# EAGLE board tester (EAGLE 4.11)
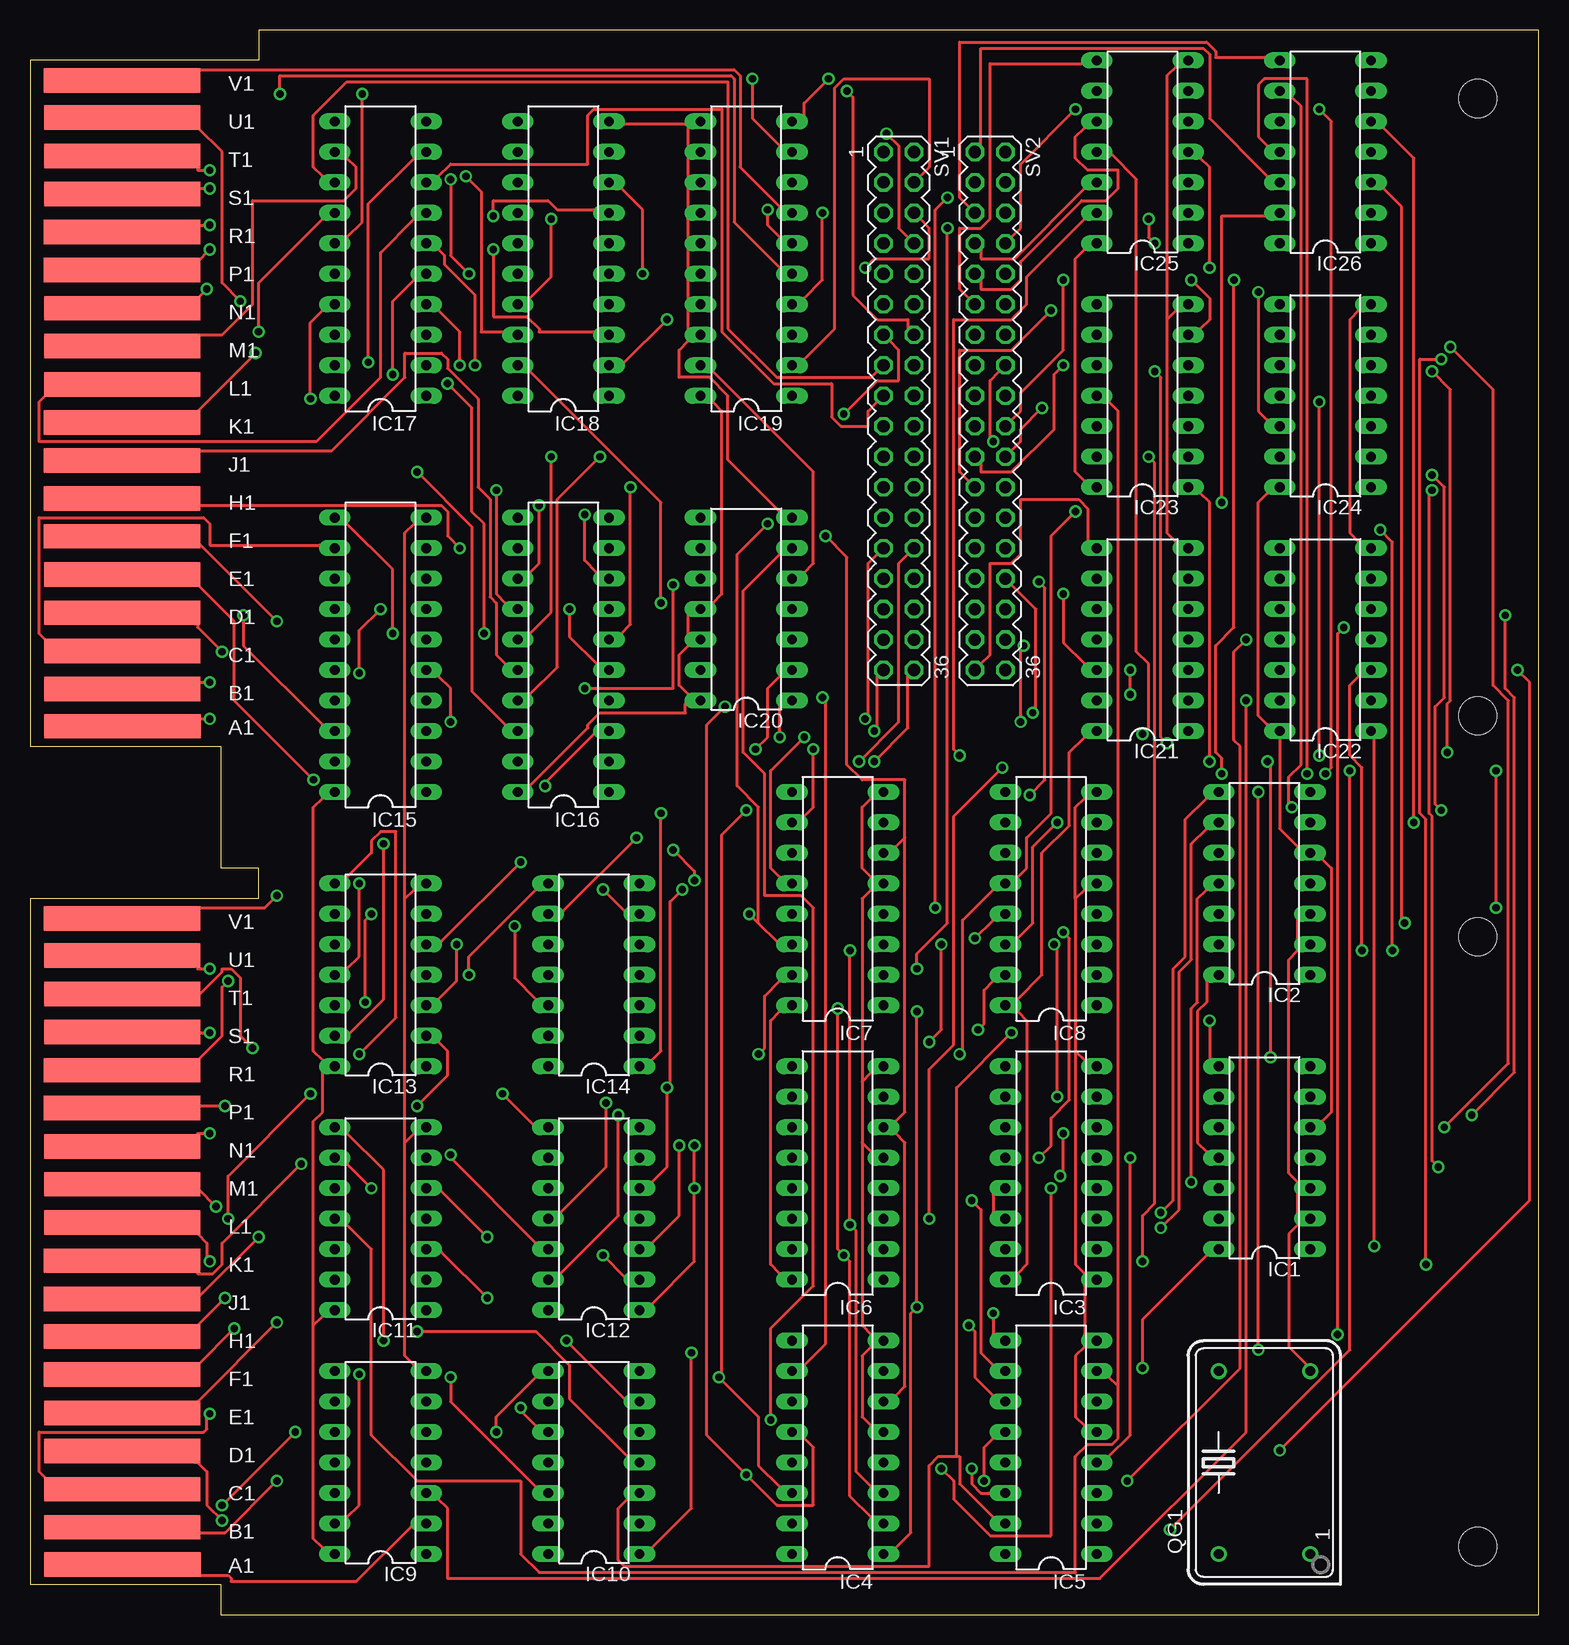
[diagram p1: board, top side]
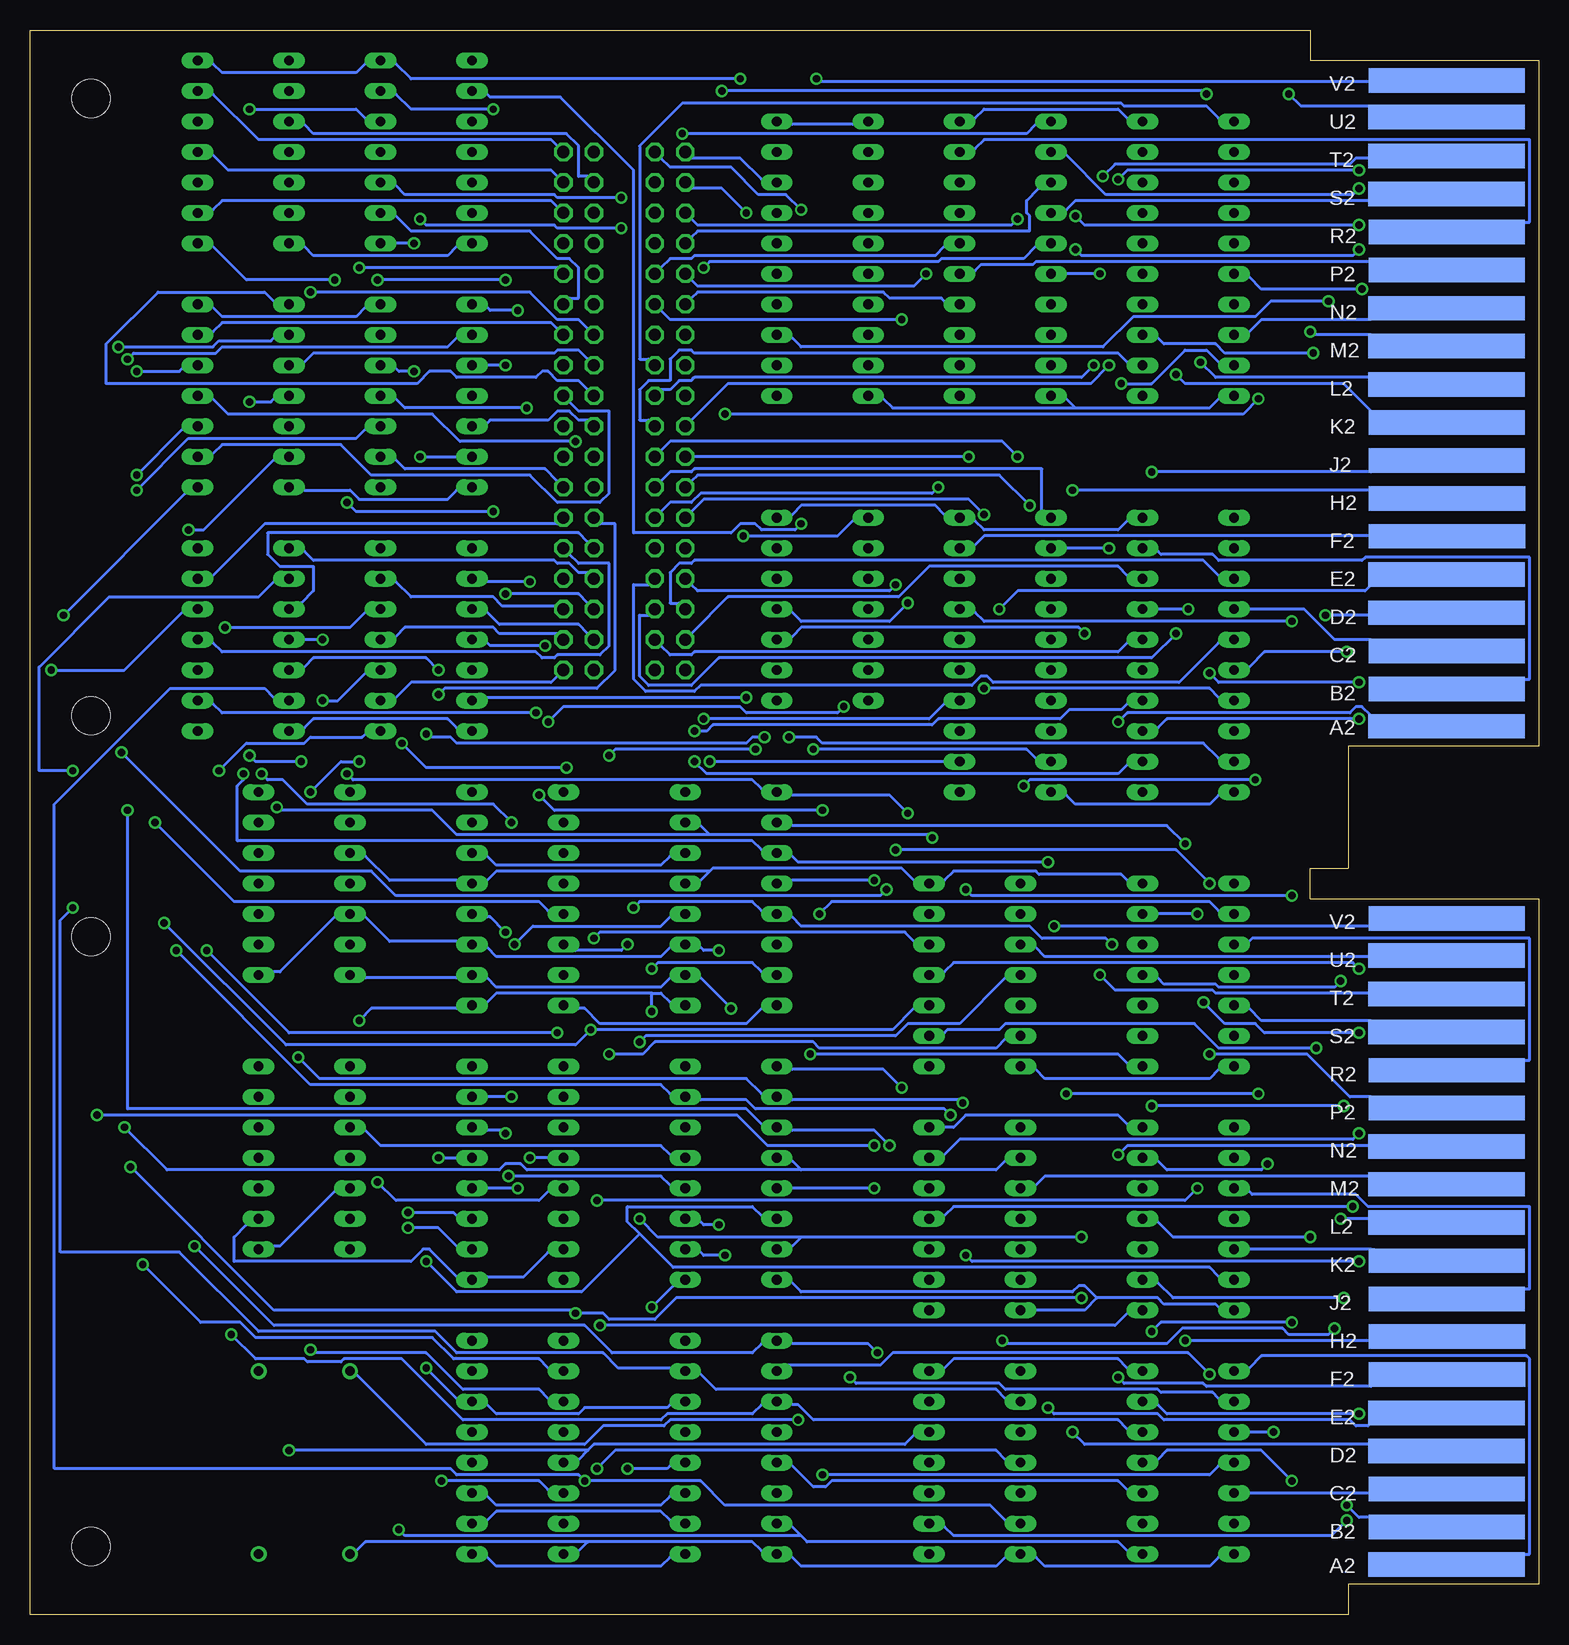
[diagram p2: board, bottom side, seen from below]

Size 125.73 x 132.08 mm. Coordinates in mm from the lower left corner, seen from the top.
Copper layers (1*16): Top 0.035mm / dielectric 1.5mm / Bottom 0.035mm
Design rules "olimex8mil": minimum track width 10mil, minimum drill 24mil, track to track 8mil, track to pad 8mil, pad to pad 8mil, via to via 8mil, smd to smd 8mil, copper to edge 25mil, drill to drill 10mil, minimum pad ring 10mil, minimum via ring 8mil, stop-mask expansion 0mil, vias tented up to drill 0mil, thermal gap 10mil

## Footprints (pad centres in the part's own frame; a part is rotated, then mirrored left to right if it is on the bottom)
DIL14 = drill 0.813 long: 1 -7.62,-3.81; 2 -5.08,-3.81; 3 -2.54,-3.81; 4 0,-3.81; 5 2.54,-3.81; 6 5.08,-3.81; 7 7.62,-3.81; 8 7.62,3.81; 9 5.08,3.81; 10 2.54,3.81; 11 0,3.81; 12 -2.54,3.81; 13 -5.08,3.81; 14 -7.62,3.81
DIL16 = drill 0.813 long: 1 -8.89,-3.81; 2 -6.35,-3.81; 3 -3.81,-3.81; 4 -1.27,-3.81; 5 1.27,-3.81; 6 3.81,-3.81; 7 6.35,-3.81; 8 8.89,-3.81; 9 8.89,3.81; 10 6.35,3.81; 11 3.81,3.81; 12 1.27,3.81; 13 -1.27,3.81; 14 -3.81,3.81; 15 -6.35,3.81; 16 -8.89,3.81
DIL20 = drill 0.813 long: 1 -11.43,-3.81; 2 -8.89,-3.81; 3 -6.35,-3.81; 4 -3.81,-3.81; 5 -1.27,-3.81; 6 1.27,-3.81; 7 3.81,-3.81; 8 6.35,-3.81; 9 8.89,-3.81; 10 11.43,-3.81; 11 11.43,3.81; 12 8.89,3.81; 13 6.35,3.81; 14 3.81,3.81; 15 1.27,3.81; 16 -1.27,3.81; 17 -3.81,3.81; 18 -6.35,3.81; 19 -8.89,3.81; 20 -11.43,3.81
DIL14S = drill 0.813 round: 1 -7.62,-3.81; 7 7.62,-3.81; 8 7.62,3.81; 14 -7.62,3.81
MA18-2 = drill 1.016 octagon: 1 -21.59,-1.27; 2 -21.59,1.27; 3 -19.05,-1.27; 4 -19.05,1.27; 5 -16.51,-1.27; 6 -16.51,1.27; 7 -13.97,-1.27; 8 -13.97,1.27; 9 -11.43,-1.27; 10 -11.43,1.27; 11 -8.89,-1.27; 12 -8.89,1.27; 13 -6.35,-1.27; 14 -6.35,1.27; 15 -3.81,-1.27; 16 -3.81,1.27; 17 -1.27,-1.27; 18 -1.27,1.27; 19 1.27,-1.27; 20 1.27,1.27; 21 3.81,-1.27; 22 3.81,1.27; 23 6.35,-1.27; 24 6.35,1.27; 25 8.89,-1.27; 26 8.89,1.27; 27 11.43,-1.27; 28 11.43,1.27; 29 13.97,-1.27; 30 13.97,1.27; 31 16.51,-1.27; 32 16.51,1.27; 33 19.05,-1.27; 34 19.05,1.27; 35 21.59,-1.27; 36 21.59,1.27
DOUBLE = smd 13.017 x 2.032: AA1 7.709,4.207; AB1 7.684,7.312; AC1 7.684,10.474; AD1 7.684,13.665; AE1 7.693,16.84; AF1 7.668,20.041; AH1 7.668,23.19; AJ1 7.668,26.34; AK1 7.668,29.515; AL1 7.693,32.69; AM1 7.693,35.89; AN1 7.693,39.04; AP1 7.668,42.24; AR1 7.668,45.39; AS1 7.693,48.565; AT1 7.693,51.74; AU1 7.693,54.94; AV1 7.668,58.026; BA1 7.709,74.057; BB1 7.684,77.162; BC1 7.684,80.324; BD1 7.684,83.515; BE1 7.693,86.69; BF1 7.668,89.891; BH1 7.668,93.04; BJ1 7.668,96.19; BK1 7.668,99.365; BL1 7.693,102.54; BM1 7.693,105.74; BN1 7.693,108.89; BP1 7.668,112.09; BR1 7.668,115.24; BS1 7.693,118.415; BT1 7.693,121.59; BU1 7.693,124.79; BV1 7.668,127.876 | smd 13.017 x 2.032 bottom: AA2 7.69,4.207; AB2 7.668,7.328; AC2 7.668,10.49; AD2 7.693,13.665; AE2 7.693,16.84; AF2 7.642,20.041; AH2 7.642,23.19; AJ2 7.668,26.34; AK2 7.668,29.515; AL2 7.693,32.69; AM2 7.693,35.89; AN2 7.693,39.04; AP2 7.668,42.24; AR2 7.668,45.39; AS2 7.693,48.565; AT2 7.693,51.74; AU2 7.693,54.966; AV2 7.668,58.026; BA2 7.69,74.057; BB2 7.668,77.178; BC2 7.668,80.34; BD2 7.693,83.515; BE2 7.693,86.69; BF2 7.642,89.891; BH2 7.642,93.04; BJ2 7.668,96.19; BK2 7.668,99.365; BL2 7.693,102.54; BM2 7.693,105.74; BN2 7.693,108.89; BP2 7.668,112.09; BR2 7.668,115.24; BS2 7.693,118.415; BT2 7.693,121.59; BU2 7.693,124.816; BV2 7.668,127.876 | hole 3.175: 120.65,56.515; 120.65,5.715; 120.65,74.93; 120.65,126.365

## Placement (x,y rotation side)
IC1  74LS93N  [DIL14]  102.87,38.1 90 top
IC2  74LS93N  [DIL14]  102.87,60.96 90 top
IC3  74LS139N  [DIL16]  85.09,36.83 90 top
IC4  74LS138N  [DIL16]  67.31,13.97 90 top
IC5  74LS138N  [DIL16]  85.09,13.97 90 top
IC6  74LS138N  [DIL16]  67.31,36.83 90 top
IC7  74LS138N  [DIL16]  67.31,59.69 90 top
IC8  74LS138N  [DIL16]  85.09,59.69 90 top
IC9  74LS07N  [DIL14]  29.21,12.7 90 top
IC10  74LS07N  [DIL14]  46.99,12.7 90 top
IC11  74LS07N  [DIL14]  29.21,33.02 90 top
IC12  74LS07N  [DIL14]  46.99,33.02 90 top
IC13  74LS07N  [DIL14]  29.21,53.34 90 top
IC14  74LS07N  [DIL14]  46.99,53.34 90 top
IC15  74LS682N  [DIL20]  29.21,80.01 90 top
IC16  74LS682N  [DIL20]  44.45,80.01 90 top
IC17  74LS682N  [DIL20]  29.21,113.03 90 top
IC18  74LS682N  [DIL20]  44.45,113.03 90 top
IC19  74LS682N  [DIL20]  59.69,113.03 90 top
IC20  74LS30N  [DIL14]  59.69,83.82 90 top
IC21  74LS07N  [DIL14]  92.71,81.28 90 top
IC22  74LS07N  [DIL14]  107.95,81.28 90 top
IC23  74LS07N  [DIL14]  92.71,101.6 90 top
IC24  74LS07N  [DIL14]  107.95,101.6 90 top
IC25  74LS07N  [DIL14]  92.71,121.92 90 top
IC26  74LS07N  [DIL14]  107.95,121.92 90 top
QG1  [DIL14S]  102.87,12.7 90 top
SV1  [MA18-2]  72.39,100.33 270 top
SV2  [MA18-2]  80.01,100.33 270 top
U$1  [DOUBLE]  0,0 0 top

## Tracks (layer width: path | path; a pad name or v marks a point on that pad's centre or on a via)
A1  (via drill 0.61)
  Top 0.254: v109.98,70.36 109.98,22.1 v95,7.11
  Bottom 0.254: 61.47,6.6 62.23,7.37 IC4.15 | 61.47,6.6 60.96,6.1 35.05,6.1 34.29,5.33 IC9.1 | v109.98,70.36 107.7,72.64 102.87,72.64 102.36,73.15 98.04,73.15 97.79,73.41 IC21.1 | v95,7.11 94.49,6.6 61.47,6.6
A2  (via drill 0.61)
  Top 0.254: IC4.14 62.48,10.67 60.71,12.45 60.71,16.51 v57.4,19.81 57.66,20.07 57.66,65.02 v59.69,67.06 | v84.07,86.11 84.58,85.6 84.58,69.6 v83.31,68.33
  Bottom 0.254: v57.4,19.81 56.9,19.3 44.96,19.3 44.45,18.8 31.75,18.8 31.5,18.54 27.18,18.54 26.67,18.03 IC9.9 | v84.07,86.11 87.63,86.11 IC21.9 | v83.31,68.33 82.04,67.06 v59.69,67.06
AA1
  Top 0.254: IC9.2 31.75,7.37 27.18,2.79 16.76,2.79 16.76,3.05 16.51,3.3 13.97,3.3 U$1.AA1
AA2
  Bottom 0.254: IC9.8 24.13,20.57 23.11,21.59 1.02,21.59 0.76,21.34 0.76,5.08 1.27,5.08 U$1.AA2
AB1  (via drill 0.61)
  Top 0.254: v20.57,11.18 16.26,6.86 13.97,6.86 U$1.AB1
  Bottom 0.254: v20.57,11.18 23.11,13.72 30.99,13.72 31.75,12.95 IC9.4
AB2  (via drill 0.61)
  Top 0.254: v16,9.14 v22.1,15.24
  Bottom 0.254: v22.1,15.24 24.13,15.24 IC9.10 | v16,9.14 14.99,8.13 13.97,8.13 U$1.AB2
AC1  (via drill 0.61)
  Top 0.254: v14.99,16.76 14.73,16.51 14.73,15.49 14.48,15.24 0.76,15.24 0.76,11.94 1.27,11.43 U$1.AC1
  Bottom 0.254: v14.99,16.76 30.99,16.76 31.75,17.53 IC9.6
AC2
  Bottom 0.254: IC9.12 24.13,10.16 13.97,10.16 U$1.AC2
AD1  (via drill 0.61)
  Top 0.254: v16,7.87 14.73,9.14 14.73,11.94 13.97,12.7 U$1.AD1
  Bottom 0.254: v16,7.87 17.27,6.6 48.77,6.6 49.53,7.37 IC10.2
AD2  (via drill 0.61)
  Top 0.254: v38.86,15.24 38.86,16.51 42.16,19.81 IC10.8
  Bottom 0.254: v38.86,15.24 37.85,14.22 13.97,14.22 U$1.AD2
ADD0  (via drill 0.61)
  Top 0.254: v98.3,49.53 98.3,46.23 IC1.8 | IC4.1 72.14,5.59 73.41,6.86 73.41,25.15 v73.91,25.65 73.91,25.91 v73.91,50.29
  Bottom 0.254: 73.91,51.82 86.87,51.82 87.63,51.05 IC8.1 90.17,50.55 97.28,50.55 v98.3,49.53 | 73.91,51.82 73.15,51.82 72.39,51.05 IC7.1 | IC4.1 72.39,4.83 73.15,4.06 86.87,4.06 87.63,4.83 IC5.1 | v73.91,25.65 72.14,27.43 IC6.1 | v73.91,50.29 73.91,51.82
ADD1  (via drill 0.61)
  Top 0.254: IC4.2 70.1,8.13 68.33,9.91 68.33,29.46 v67.82,29.97 67.56,30.23 67.31,30.48 v67.31,50.55 | IC1.11 98.04,38.61 97.28,39.37 97.28,50.29 98.04,51.05 98.04,52.83 IC2.14
  Bottom 0.254: IC4.2 72.39,7.87 73.15,8.64 86.87,8.64 87.63,7.87 IC5.2 | v67.82,29.97 69.6,29.97 69.85,30.23 IC6.2 | IC2.14 97.79,53.09 90.17,53.09 IC8.2 87.63,53.09 86.87,52.32 73.15,52.32 72.39,53.09 IC7.2 69.85,53.09 v67.31,50.55
ADD2  (via drill 0.61)
  Top 0.254: IC4.3 70.1,10.67 68.83,11.94 68.83,32 v68.33,32.51 68.33,32.77 v68.33,55.37
  Bottom 0.254: IC2.1 105.41,53.59 104.9,53.59 100.33,58.17 IC2.12 97.79,58.17 95.76,56.13 90.17,56.13 IC8.3 87.63,55.63 86.87,54.86 73.15,54.86 72.39,55.63 IC7.3 69.85,55.63 69.6,55.37 v68.33,55.37 | IC4.3 72.39,9.91 73.15,9.14 86.87,9.14 87.63,9.91 IC5.3 | v68.33,32.51 69.6,32.51 69.85,32.77 IC6.3
ADD3  (via drill 0.61)
  Top 0.254: v94.23,32.26 95.76,33.78 95.76,53.59 96.77,54.61 96.77,64.26 98.04,65.53 IC2.9
  Bottom 0.254: v94.23,32.26 91.69,32.26 90.17,30.73 IC3.2
ADD4  (via drill 0.61)
  Top 0.254: v94.23,33.53 95.25,34.54 95.25,53.85 96.27,54.86 96.27,66.29 98.04,68.07 IC2.8
  Bottom 0.254: v94.23,33.53 90.42,33.53 90.17,33.27 IC3.3
ADD5  (via drill 0.61)
  Top 0.254: IC3.14 80.26,33.53 80.26,35.05 IC3.13 | v96.77,36.07 96.77,50.55 97.28,51.05 97.28,59.69 98.04,60.45 IC2.11
  Bottom 0.254: v96.77,36.07 95.25,34.54 83.31,34.54 82.55,35.31 IC3.13
AE1  (via drill 0.61)
  Top 0.254: v32.26,23.62 42.16,23.62 44.96,20.83 44.96,18.03 49.78,13.21 IC10.4 | v20.57,24.38 13.97,17.78 U$1.AE1
  Bottom 0.254: v32.26,23.62 31.5,24.38 v20.57,24.38
AE2  (via drill 0.61)
  Top 0.254: v40.89,17.27 40.89,17.02 42.16,15.75 IC10.10
  Bottom 0.254: v40.89,17.27 40.39,16.76 31.75,16.76 31.24,16.26 15.75,16.26 15.24,15.75 14.22,15.75 13.97,16 U$1.AE2
AF1  (via drill 0.61)
  Top 0.254: v44.7,22.86 49.53,18.03 IC10.6 | v17.02,23.88 13.97,20.83 U$1.AF1
  Bottom 0.254: v44.7,22.86 44.45,22.61 30.99,22.61 29.72,23.88 21.34,23.88 20.83,23.37 17.53,23.37 v17.02,23.88
AF2  (via drill 0.61)
  Top 0.254: v35.05,19.81 35.05,17.78 42.16,10.67 IC10.12
  Bottom 0.254: v35.05,19.81 34.54,19.3 27.94,19.3 27.69,19.05 13.97,19.05 U$1.AF2
AH1  (via drill 0.61)
  Top 0.254: v16.26,26.42 13.97,24.13 U$1.AH1
  Bottom 0.254: v16.26,26.42 30.48,26.42 31.75,27.69 IC11.2
AH2  (via drill 0.61)
  Top 0.254: v29.46,22.86 29.46,37.08 26.42,40.13 IC11.8
  Bottom 0.254: v29.46,22.86 13.97,22.86 U$1.AH2
AJ1  (via drill 0.61)
  Top 0.254: v19.05,31.5 13.97,26.42 U$1.AJ1
  Bottom 0.254: v19.05,31.5 30.48,31.5 31.75,32.77 IC11.4
AJ2
  Bottom 0.254: IC11.10 24.13,35.31 23.88,35.05 15.24,35.05 14.22,34.04 0.76,34.04 0.76,27.18 1.27,27.18 U$1.AJ2
AK1  (via drill 0.61)
  Top 0.254: v22.61,37.59 16,30.99 16,29.21 15.24,28.45 13.97,28.45 13.97,28.7 U$1.AK1
  Bottom 0.254: v22.61,37.59 23.11,37.08 30.99,37.08 31.75,37.85 IC11.6
AK2
  Bottom 0.254: IC11.12 24.13,30.48 13.97,30.48 U$1.AK2
AL1  (via drill 0.61)
  Top 0.254: v47.75,29.97 49.53,28.19 IC12.2 | v14.99,29.46 14.73,29.72 14.73,30.99 13.97,31.75 U$1.AL1
  Bottom 0.254: v47.75,29.97 47.24,29.46 v14.99,29.46
AL2  (via drill 0.61)
  Top 0.254: v39.37,43.43 41.91,40.89 IC12.8 | v23.37,43.43 16.51,36.58 v16.51,33.02
  Bottom 0.254: v23.37,43.43 v39.37,43.43 | v16.51,33.02 13.97,33.02 U$1.AL2
AM1  (via drill 0.61)
  Top 0.254: v15.49,34.04 13.97,35.56 U$1.AM1
  Bottom 0.254: v15.49,34.04 48.77,34.04 49.53,33.27 IC12.4
AM2
  Bottom 0.254: IC12.10 41.91,35.81 41.15,36.58 13.97,36.58 U$1.AM2
AN1  (via drill 0.61)
  Top 0.254: v14.99,40.13 13.97,40.13 13.97,39.88 U$1.AN1
  Bottom 0.254: v14.99,40.13 15.49,39.62 48.26,39.62 49.53,38.35 IC12.6
AN2  (via drill 0.61)
  Top 0.254: v35.05,38.35 35.05,38.1 42.16,30.99 IC12.12
  Bottom 0.254: v35.05,38.35 34.29,39.12 13.97,39.12 U$1.AN2
AP1  (via drill 0.61)
  Top 0.254: v32.26,42.42 34.8,44.96 34.8,46.99 34.04,47.75 IC13.2 | v16.26,42.42 13.97,42.42 U$1.AP1
  Bottom 0.254: v16.26,42.42 v32.26,42.42
AP2  (via drill 0.61)
  Top 0.254: v27.43,46.74 30.48,49.78 30.48,65.28 29.21,65.28 28.45,64.52 28.45,63.5 26.42,61.47 IC13.8
  Bottom 0.254: v27.43,46.74 19.3,46.74 15.75,43.18 13.97,43.18 U$1.AP2
AR1  (via drill 0.61)
  Top 0.254: v16.51,52.83 16,52.32 16,48.26 13.97,46.23 U$1.AR1
  Bottom 0.254: v16.51,52.83 17.02,52.32 26.67,52.32 26.92,52.58 31.24,52.58 31.75,53.09 IC13.4
AR2
  Bottom 0.254: IC13.10 24.13,56.13 23.88,56.39 0.76,56.39 0.76,46.23 1.27,46.23 U$1.AR2
AS1  (via drill 0.61)
  Top 0.254: v28.45,58.42 27.94,57.91 v27.94,51.05 | v14.99,48.51 13.97,48.51 U$1.AS1
  Bottom 0.254: v28.45,58.42 31.75,58.42 IC13.6 | v27.94,51.05 26.16,49.28 23.62,49.28 22.86,48.51 v14.99,48.51
AS2
  Bottom 0.254: IC13.12 24.13,50.55 23.11,49.53 13.97,49.53 U$1.AS2
AT1  (via drill 0.61)
  Top 0.254: v18.54,47.24 17.53,48.26 17.53,53.09 16.76,53.85 16,53.85 16,53.59 13.97,51.56 U$1.AT1
  Bottom 0.254: v18.54,47.24 26.67,47.24 28.7,49.28 44.45,49.28 44.96,48.77 49.28,48.77 49.53,48.51 IC14.2
AT2  (via drill 0.61)
  Top 0.254: v36.58,53.34 36.58,54.86 42.16,60.45 IC14.8
  Bottom 0.254: v36.58,53.34 35.31,52.07 27.18,52.07 26.92,51.82 13.97,51.82 U$1.AT2
AU1  (via drill 0.61)
  Top 0.254: v14.99,53.85 13.97,53.85 13.97,54.1 U$1.AU1
  Bottom 0.254: v14.99,53.85 15.49,54.36 48.77,54.36 49.53,53.59 IC14.4
AU2
  Bottom 0.254: IC14.10 41.91,55.63 41.15,54.86 13.97,54.86 U$1.AU2
AV1  (via drill 0.61)
  Top 0.254: v47.75,60.45 49.53,58.67 IC14.6 | v20.57,59.94 19.56,58.93 13.97,58.93 U$1.AV1
  Bottom 0.254: v47.75,60.45 47.24,59.94 v20.57,59.94
AV2  (via drill 0.61)
  Top 0.254: v40.39,57.4 40.39,53.09 42.16,51.31 IC14.12
  Bottom 0.254: v40.39,57.4 13.97,57.4 U$1.AV2
B1  (via drill 0.61)
  Top 0.254: v101.35,76.2 101.35,15.24 89.15,3.05 34.8,3.05 34.8,8.89 34.04,9.65 IC9.3
  Bottom 0.254: IC9.3 34.29,10.41 35.05,11.18 58.93,11.18 59.44,10.67 60.45,10.67 62.23,12.45 IC4.13 | v101.35,76.2 100.08,76.2 97.79,78.49 IC21.3
B2  (via drill 0.61)
  Top 0.254: IC4.12 64.52,14.73 65.28,13.97 65.28,9.14 62.23,9.14 v59.69,11.68 59.44,11.94 56.39,14.99 56.39,74.17 v57.91,75.69 | v82.8,80.77 82.55,80.52 v82.55,74.42
  Bottom 0.254: v59.69,11.68 27.43,11.68 26.67,12.45 IC9.11 | v82.8,80.77 87.38,80.77 87.63,81.03 IC21.11 | v82.55,74.42 81.28,75.69 66.55,75.69 66.04,75.18 58.42,75.18 v57.91,75.69
BA1  (via drill 0.61)
  Top 0.254: v14.99,74.68 13.97,74.68 U$1.BA1
  Bottom 0.254: v14.99,74.68 30.99,74.68 31.75,73.91 IC15.3
BA2  (via drill 0.61)
  Top 0.254: v35.05,74.42 35.05,77.22 34.04,78.23 IC15.5
  Bottom 0.254: v35.05,74.42 34.29,75.18 15.75,75.18 15.24,75.69 14.73,75.69 13.97,74.93 U$1.BA2
BB1  (via drill 0.61)
  Top 0.254: v29.21,83.82 27.43,82.04 v27.43,78.49 | v14.99,77.72 13.97,77.72 U$1.BB1
  Bottom 0.254: v29.21,83.82 31.75,83.82 IC15.7 | v27.43,78.49 26.67,77.72 v14.99,77.72
BB2
  Bottom 0.254: IC15.9 31.75,88.65 31.5,88.39 27.18,88.39 26.67,87.88 14.73,87.88 14.48,88.14 0.76,88.14 0.76,77.98 1.27,77.98 U$1.BB2
BC1
  Top 0.254: IC15.12 24.13,89.15 14.99,89.15 14.99,90.93 14.48,91.44 0.76,91.44 0.76,81.79 1.27,81.28 U$1.BC1
BC2
  Bottom 0.254: IC15.14 24.13,83.82 19.56,83.82 17.02,81.28 13.97,81.28 U$1.BC2
BD1  (via drill 0.61)
  Top 0.254: v16,80.26 13.97,82.3 13.97,82.55 U$1.BD1
  Bottom 0.254: v16,80.26 22.86,80.26 24.13,78.99 IC15.16
BD2  (via drill 0.61)
  Top 0.254: v17.78,83.31 17.78,80.77 24.38,74.17 IC15.18
  Bottom 0.254: v17.78,83.31 13.97,83.31 U$1.BD2
BE1  (via drill 0.61)
  Top 0.254: v42.93,69.09 42.93,69.34 46.99,73.41 IC16.3 | v23.62,69.6 17.02,76.2 17.02,82.8 13.97,85.85 U$1.BE1
  Bottom 0.254: v42.93,69.09 42.42,69.6 v23.62,69.6
BE2  (via drill 0.61)
  Top 0.254: v44.96,83.82 44.96,81.53 47.24,79.25 IC16.5
  Bottom 0.254: v44.96,83.82 43.43,85.34 14.48,85.34 13.97,85.85 U$1.BE2
BF1  (via drill 0.61)
  Top 0.254: v20.57,82.8 13.97,89.41 U$1.BF1
  Bottom 0.254: v20.57,82.8 46.23,82.8 46.99,83.57 IC16.7
BF2
  Bottom 0.254: IC16.9 46.99,89.15 46.23,89.92 13.97,89.92 U$1.BF2
BH1  (via drill 0.61)
  Top 0.254: v35.81,88.9 34.8,89.92 34.8,91.95 34.29,92.46 13.97,92.46 U$1.BH1
  Bottom 0.254: v35.81,88.9 39.37,88.9 IC16.12
BH2  (via drill 0.61)
  Top 0.254: v38.86,93.73 38.86,85.09 39.62,84.33 IC16.14
  Bottom 0.254: v38.86,93.73 13.97,93.73 U$1.BH2
BJ1
  Top 0.254: IC16.16 39.62,79.25 38.86,80.01 38.86,84.33 38.35,84.84 38.35,92.96 37.34,93.98 37.34,101.35 34.8,103.89 34.8,104.65 34.29,105.16 31.24,105.16 31.24,103.12 25.15,97.03 13.97,97.03 U$1.BJ1
BJ2  (via drill 0.61)
  Top 0.254: v32.26,95.25 36.83,90.68 36.83,76.96 39.62,74.17 IC16.18
  Bottom 0.254: v32.26,95.25 13.97,95.25 U$1.BJ2
BK1  (via drill 0.61)
  Top 0.254: v18.8,105.16 13.97,100.33 U$1.BK1
  Bottom 0.254: v18.8,105.16 26.16,105.16 26.92,105.92 31.24,105.92 31.75,106.43 IC17.3
BK2  (via drill 0.61)
  Top 0.254: v30.23,103.38 30.23,109.47 32,111.25 IC17.5
  Bottom 0.254: v30.23,103.38 29.46,102.62 16.26,102.62 13.97,100.33 U$1.BK2
BL1
  Top 0.254: IC17.7 32,116.33 29.21,113.54 29.21,103.12 23.88,97.79 0.76,97.79 0.76,101.09 1.27,101.6 U$1.BL1
BL2  (via drill 0.61)
  Top 0.254: v28.19,104.39 28.19,117.6 32,121.41 IC17.9
  Bottom 0.254: v28.19,104.39 26.92,103.12 13.97,103.12 U$1.BL2
BM1
  Top 0.254: IC17.12 26.42,121.41 27.18,120.65 27.18,118.87 26.16,117.86 18.54,117.86 18.54,109.22 16,106.68 13.97,106.68 U$1.BM1
BM2  (via drill 0.61)
  Top 0.254: v19.05,106.93 19.05,111 24.38,116.33 IC17.14
  Bottom 0.254: v19.05,106.93 18.8,106.68 13.97,106.68 U$1.BM2
BN1  (via drill 0.61)
  Top 0.254: v14.73,110.49 13.97,109.73 U$1.BN1
  Bottom 0.254: v14.73,110.49 23.11,110.49 24.13,111.51 IC17.16
BN2
  Bottom 0.254: IC17.18 24.13,106.93 23.11,107.95 13.97,107.95 U$1.BN2
BP1  (via drill 0.61)
  Top 0.254: v38.61,113.79 38.61,108.2 41.4,108.2 42.42,107.19 42.42,106.93 46.99,106.93 IC18.3 | v14.99,113.79 13.97,112.78 U$1.BP1
  Bottom 0.254: v38.61,113.79 38.1,113.28 15.49,113.28 v14.99,113.79
BP2
  Bottom 0.254: IC18.5 46.99,112.01 46.48,112.52 42.16,112.52 41.91,112.78 13.97,112.78 U$1.BP2
BR1  (via drill 0.61)
  Top 0.254: v38.61,116.59 38.61,117.86 43.18,117.86 43.94,117.09 46.99,117.09 IC18.7 | v14.99,115.82 13.97,115.82 U$1.BR1
  Bottom 0.254: v38.61,116.59 37.85,115.82 v14.99,115.82
BR2
  Bottom 0.254: IC18.9 46.99,122.17 46.23,122.94 0.76,122.94 0.76,116.08 1.27,116.08 U$1.BR2
BS1  (via drill 0.61)
  Top 0.254: v14.99,118.87 13.97,118.87 U$1.BS1
  Bottom 0.254: v14.99,118.87 15.49,118.36 36.07,118.36 39.37,121.67 IC18.12
BS2
  Bottom 0.254: IC18.14 39.37,117.09 38.61,117.86 13.97,117.86 U$1.BS2
BT1  (via drill 0.61)
  Top 0.254: v36.58,111.76 35.05,113.28 v35.05,119.63 | v14.99,120.4 13.97,120.4 13.97,120.65 U$1.BT1
  Bottom 0.254: v36.58,111.76 39.37,111.76 IC18.16 | v35.05,119.63 34.29,120.4 v14.99,120.4
BT2  (via drill 0.61)
  Top 0.254: v36.32,119.89 37.59,118.62 37.59,106.93 39.37,106.93 IC18.18
  Bottom 0.254: v36.32,119.89 35.31,120.9 15.75,120.9 15.24,121.41 13.97,121.41 U$1.BT2
BU1  (via drill 0.61)
  Top 0.254: v17.53,109.47 16,111 16,121.92 13.97,123.95 U$1.BU1
  Bottom 0.254: v17.53,109.47 22.35,109.47 23.62,108.2 33.78,108.2 36.32,105.66 61.47,105.66 62.23,106.43 IC19.3
BU2  (via drill 0.61)
  Top 0.254: v20.83,126.75 20.83,128.27 58.42,128.27 58.67,128.02 58.67,116.08 62.48,112.27 IC19.5
  Bottom 0.254: v20.83,126.75 19.81,125.73 13.97,125.73 U$1.BU2
BV1
  Top 0.254: IC19.7 62.48,117.35 59.18,120.65 59.18,128.27 58.67,128.78 13.97,128.78 U$1.BV1
BV2  (via drill 0.61)
  Top 0.254: v60.2,128.02 60.2,124.71 62.48,122.43 IC19.9
  Bottom 0.254: v60.2,128.02 59.94,127.76 13.97,127.76 U$1.BV2
C1  (via drill 0.61)
  Top 0.254: v109.47,82.3 108.97,81.79 v108.97,23.37
  Bottom 0.254: IC9.5 34.29,15.49 35.05,16.26 60.45,16.26 61.72,17.53 62.23,17.53 IC4.11 64.77,17.53 65.53,16.76 72.64,16.76 73.15,16.26 89.66,16.26 94.74,21.34 99.57,21.34 99.82,21.08 102.62,21.08 102.87,21.34 106.93,21.34 v108.97,23.37 | v109.47,82.3 99.06,82.3 97.79,83.57 IC21.5
C2  (via drill 0.61)
  Top 0.254: v27.43,20.07 27.43,9.14 26.42,8.13 IC9.13 | v66.04,76.45 66.29,76.2 66.29,22.61 64.52,20.83 IC4.10
  Bottom 0.254: v27.43,20.07 29.21,21.84 53.85,21.84 54.86,20.83 62.48,20.83 IC4.10 | v66.04,76.45 87.63,76.45 IC21.13
CLK1
  Bottom 0.254: IC1.12 100.33,35.31 104.9,30.73 105.41,30.73 IC1.1
D1  (via drill 0.61)
  Top 0.254: v55.12,21.84 55.12,8.89 51.82,5.59 IC10.1 | v112.01,30.73 112.01,73.15 IC22.1
  Bottom 0.254: v55.12,21.84 55.88,22.61 62.23,22.61 IC4.9 64.77,22.61 65.53,21.84 77.22,21.84 79.5,24.13 105.41,24.13 v112.01,30.73
D2  (via drill 0.61)
  Top 0.254: v122.17,58.93 v122.17,70.36
  Bottom 0.254: IC10.9 44.45,18.03 45.21,18.8 68.58,18.8 69.85,20.07 IC4.7 72.39,20.57 76.71,20.57 77.98,21.84 90.17,21.84 91.95,23.62 106.68,23.62 113.28,30.23 123.19,30.23 123.19,57.91 v122.17,58.93 | v122.17,70.36 124.97,70.36 124.97,78.99 119.13,84.84 106.68,84.84 105.41,86.11 IC22.9
E1  (via drill 0.61)
  Top 0.254: 77.22,13.21 77.47,13.21 77.47,10.92 80.26,8.13 IC5.15 | 77.22,13.21 75.69,13.21 74.93,12.45 74.93,4.06 49.53,4.06 49.02,4.57 49.02,8.89 49.78,9.65 IC10.3 | v111,55.37 111,70.61 109.98,71.63 109.98,77.47 110.74,78.23 IC22.3 | v81.79,48.51 77.22,43.94 77.22,13.21
  Bottom 0.254: v111,55.37 104.14,48.51 v81.79,48.51
E2  (via drill 0.61)
  Top 0.254: v78.49,12.19 78.49,10.92 79.25,10.16 80.01,10.16 IC5.14 | v101.35,81.28 100.33,80.26 100.33,72.9 100.84,72.39 100.84,20.57 v91.44,11.18
  Bottom 0.254: v78.49,12.19 76.96,13.72 45.21,13.72 44.45,12.95 IC10.11 | v101.35,81.28 102.87,81.28 IC22.11 | v91.44,11.18 83.31,11.18 82.55,10.41 IC5.14
F1  (via drill 0.61)
  Top 0.254: v123.95,78.74 124.97,77.72 124.97,34.54 v104.14,13.72
  Bottom 0.254: 79.25,13.72 80.01,12.95 IC5.13 | 79.25,13.72 78.74,14.22 52.83,14.22 52.07,14.99 IC10.5 | v123.95,78.74 117.86,78.74 113.03,83.57 IC22.5 | 79.25,13.72 v104.14,13.72
F2  (via drill 0.61)
  Top 0.254: v79.5,11.18 79.5,13.97 80.26,14.73 IC5.12
  Bottom 0.254: IC10.13 44.45,7.87 45.72,9.14 67.82,9.14 69.85,11.18 v79.5,11.18 79.76,11.43 80.01,11.68 90.17,11.68 90.68,12.19 123.7,12.19 123.7,67.56 114.05,77.22 106.17,77.22 105.41,76.45 IC22.13
GND  (via drill 0.61)
  Top 0.254: IC22.7 110.74,89.41 109.98,90.17 109.98,107.95 110.74,108.71 IC24.7 | 94.74,107.95 94.74,90.17 95.5,89.41 IC21.7 | 94.74,107.95 95.5,108.71 IC23.7 | 94.74,107.95 94.74,128.27 95.5,129.03 IC25.7 | IC18.10 49.53,124.21 54.61,124.21 IC19.11 54.86,123.95 54.86,122.43 IC19.12 54.86,121.41 54.86,119.89 IC19.13 54.86,118.87 54.86,117.35 IC19.14 54.86,116.33 54.86,114.81 IC19.15 54.86,113.79 54.86,112.27 IC19.16 54.86,111.25 54.86,109.73 IC19.17 54.86,108.71 54.86,107.19 IC19.18 54.86,106.17 54.1,105.41 54.1,103.12 56.64,103.12 58.17,101.6 58.17,96.27 62.48,91.95 IC20.7 | v66.55,128.02 64.52,125.98 64.52,124.97 IC19.10 | IC2.3 105.66,57.91 105.66,56.39 IC2.2 105.66,55.37 104.9,54.61 104.9,36.83 105.66,36.07 IC1.3 105.66,35.05 105.66,33.53 IC1.2 105.66,32.51 104.9,31.75 104.9,22.35 106.43,20.83 QG1.7 | IC5.5 87.88,15.75 87.12,16.51 87.12,21.59 87.88,22.35 IC5.8 87.88,23.37 87.88,27.43 IC3.1 87.88,28.45 87.12,29.21 87.12,46.99 | 87.12,46.99 87.88,46.23 IC3.8 | 87.12,59.69 87.12,46.99 | 87.12,59.69 87.88,60.45 IC8.5 | 87.12,59.69 87.12,67.31 87.88,68.07 IC8.8 | 31.24,39.37 31.24,21.59 32,20.83 IC9.7 | 31.24,39.37 32,40.13 IC11.7 | 31.24,59.69 32,60.45 IC13.7 | 31.24,39.37 31.24,59.69 | IC7.8 70.1,68.07 69.34,67.31 69.34,62.23 70.1,61.47 IC7.5 70.1,60.45 69.34,59.69 69.34,44.45 | IC4.5 70.1,15.75 69.34,16.51 69.34,21.59 70.1,22.35 IC4.8 70.1,23.37 69.34,24.13 69.34,39.37 | 69.34,39.37 70.1,38.61 IC6.5 | 69.34,44.45 69.34,39.37 | 69.34,44.45 70.1,45.21 IC6.8 | 31.24,59.69 31.24,90.17 32,90.93 IC15.10
  Bottom 0.254: IC26.7 110.49,129.29 109.73,128.52 98.55,128.52 97.79,129.29 IC25.7 95.25,129.29 93.98,128.02 v66.55,128.02 | IC24.7 110.49,108.97 109.73,108.2 98.55,108.2 97.79,108.97 IC23.7 | IC15.10 34.29,91.19 35.05,90.42 46.23,90.42 46.99,91.19 IC16.10 49.53,91.69 50.29,92.46 61.47,92.46 62.23,91.69 IC20.7 | IC17.10 34.29,124.71 35.05,125.48 46.23,125.48 46.99,124.71 IC18.10 | IC19.10 62.23,124.21 57.15,124.21 IC19.11 | IC3.15 82.55,30.23 84.58,28.19 87.63,28.19 IC3.1 90.17,28.19 92.46,30.48 92.96,30.48 93.98,29.46 108.71,29.46 108.71,31.5 107.7,32.51 IC1.2 | IC2.10 97.79,63.25 95.76,61.21 90.17,61.21 IC8.5 87.63,61.21 86.87,61.98 69.09,61.98 | IC13.7 34.29,61.21 34.8,61.72 41.66,61.72 41.91,61.98 48.77,61.98 49.53,61.21 IC14.7 52.07,61.21 53.09,62.23 68.83,62.23 69.09,61.98 | IC9.7 34.29,20.57 35.05,21.34 48.77,21.34 49.53,20.57 IC10.7 | IC11.7 34.29,40.89 35.05,41.66 47.75,41.66 48.77,40.64 49.53,40.64 IC12.7 | IC1.10 97.79,40.39 96.52,39.12 73.15,39.12 72.39,38.35 IC6.5 | 69.09,61.98 69.85,61.21 IC7.5
H1  (via drill 0.61)
  Top 0.254: v78.23,24.13 78.74,23.62 78.74,19.81 80.26,18.29 IC5.11 | v98.3,71.12 98.3,92.71 97.54,93.47 IC23.1 | v102.36,22.1 v102.36,68.58
  Bottom 0.254: v78.23,24.13 35.31,24.13 34.29,25.15 IC11.1 | v98.3,71.12 99.82,71.12 v102.36,68.58 | v102.36,22.1 102.11,21.84 92.71,21.84 89.66,18.8 83.31,18.8 82.55,18.03 IC5.11
H2  (via drill 0.61)
  Top 0.254: v28.45,35.56 26.42,37.59 IC11.9 | v78.49,34.54 79.25,33.78 79.25,21.84 80.26,20.83 IC5.10 | v117.6,104.65 115.82,104.65 115.82,66.8 116.33,66.29 v116.33,29.21
  Bottom 0.254: v28.45,35.56 29.46,34.54 v78.49,34.54 | v117.6,104.65 117.09,105.16 110.24,105.16 109.73,105.66 90.93,105.66 90.17,106.43 IC23.9 | v116.33,29.21 111.51,24.38 108.2,24.38 106.93,23.11 92.2,23.11 90.42,21.34 83.31,21.34 82.55,20.57 IC5.10
J1  (via drill 0.61)
  Top 0.254: v38.1,26.42 34.29,30.23 IC11.3 | v80.26,25.15 80.26,23.37 IC5.9 | v116.84,93.73 116.59,93.47 116.59,66.8 116.84,66.55 116.84,37.85 v117.35,37.34
  Bottom 0.254: v38.1,26.42 71.88,26.42 73.66,24.64 77.47,24.64 77.98,25.15 v80.26,25.15 80.52,25.4 105.41,25.4 v117.35,37.34 | v116.84,93.73 112.52,98.04 98.55,98.04 97.79,98.81 IC23.3
J2
  Top 0.254: 90.68,19.05 90.68,14.73 90.17,14.22 88.14,14.22 87.12,13.21 87.12,3.56 42.42,3.56 40.89,5.08 40.89,11.18 32.26,11.18 28.45,14.99 28.45,30.48 26.42,32.51 IC11.11 | 90.68,19.05 89.92,19.81 IC5.7 | 90.68,19.05 90.68,100.33 89.92,101.09 IC23.11
K1  (via drill 0.61)
  Top 0.254: v38.1,31.5 34.29,35.31 IC11.5 | v93.73,103.63 94.23,103.12 94.23,73.15 v94.74,72.64 | v81.03,70.61 76.96,66.55 76.96,47.5 74.93,45.47 v74.93,33.02
  Bottom 0.254: v38.1,31.5 61.47,31.5 | 61.47,31.5 62.23,30.73 IC6.15 | v93.73,103.63 95,103.63 95.25,103.89 IC23.5 | v94.74,72.64 92.71,70.61 v81.03,70.61 | v74.93,33.02 73.41,31.5 61.47,31.5
K2  (via drill 0.61)
  Top 0.254: v93.22,96.52 93.73,96.01 93.73,34.29 92.71,33.27 v92.71,29.46
  Bottom 0.254: 74.93,31.75 75.95,32.77 75.95,34.04 65.53,34.04 64.77,33.27 IC6.14 | 74.93,31.75 72.14,28.96 27.43,28.96 26.67,28.19 IC11.13 | v93.22,96.52 90.17,96.52 IC23.13 | v92.71,29.46 90.17,26.92 79.76,26.92 74.93,31.75
L1  (via drill 0.61)
  Top 0.254: IC12.1 51.82,25.91 55.37,29.46 v55.37,35.56 55.37,35.81 v55.37,39.12 | v122.94,83.31 122.94,77.22 123.7,76.45 123.7,45.21 v120.14,41.66
  Bottom 0.254: v55.37,35.56 62.23,35.56 IC6.13 | v122.94,83.31 112.78,93.47 IC24.1 | v120.14,41.66 66.8,41.66 64.26,39.12 v55.37,39.12
L2  (via drill 0.61)
  Top 0.254: v118.36,105.66 121.92,102.11 121.92,77.47 123.19,76.2 123.19,45.97 v117.86,40.64
  Bottom 0.254: 61.47,37.08 45.21,37.08 44.45,37.85 IC12.9 | 61.47,37.08 62.23,37.85 IC6.12 | v118.36,105.66 110.49,105.66 109.98,106.17 105.66,106.17 105.41,106.43 IC24.9 | v117.86,40.64 114.3,37.08 86.61,37.08 86.11,37.59 84.84,37.59 84.33,37.08 61.47,37.08
M1  (via drill 0.61)
  Top 0.254: v54.1,39.12 54.1,33.27 51.82,30.99 IC12.3 | v116.84,95 117.86,93.98 117.86,76.45 117.09,75.69 117.09,67.56 v117.6,67.06
  Bottom 0.254: v54.1,39.12 55.37,40.39 62.23,40.39 IC6.11 64.77,40.89 66.04,42.16 117.6,42.16 v117.6,67.06 | v116.84,95 113.03,98.81 IC24.3
M2  (via drill 0.61)
  Top 0.254: v48.01,42.67 48.01,37.34 44.2,33.53 IC12.11 | v107.44,71.63 v107.44,101.09 | v103.12,71.12 103.38,70.87 v103.38,46.48
  Bottom 0.254: v48.01,42.67 48.26,42.93 62.23,42.93 IC6.10 64.77,43.43 66.04,44.7 101.6,44.7 v103.38,46.48 | v107.44,101.09 105.66,101.09 105.41,101.35 IC24.11 | v107.44,71.63 106.93,71.12 v103.12,71.12
N1  (via drill 0.61)
  Top 0.254: IC12.5 51.82,36.07 53.09,37.34 v53.09,43.94 53.34,44.2 53.34,59.44 v54.36,60.45 | v116.84,103.63 118.36,102.11 118.36,76.2 118.11,75.95 v118.11,71.88
  Bottom 0.254: v53.09,43.94 54.61,45.47 62.23,45.47 IC6.9 | v116.84,103.63 113.28,103.63 113.03,103.89 IC24.5 | v118.11,71.88 108.2,61.98 97.28,61.98 95.25,59.94 54.86,59.94 v54.36,60.45
N2  (via drill 0.61)
  Top 0.254: v49.02,41.66 49.02,33.27 44.2,28.45 IC12.13 | v112.52,90.42 113.54,89.41 v113.54,55.37
  Bottom 0.254: v49.02,41.66 49.53,42.16 65.28,42.16 66.04,42.93 69.85,42.93 IC6.7 72.39,43.43 73.15,44.2 102.36,44.2 v113.54,55.37 | v112.52,90.42 111.25,90.42 105.41,96.27 IC24.13
N$1  (via drill 0.61)
  Top 0.254: v61.72,16.26 61.72,23.88 65.28,27.43 65.28,58.93 64.26,59.94 61.21,59.94 61.21,70.1 59.44,71.88 59.44,85.34 62.48,88.39 IC20.6
  Bottom 0.254: v61.72,16.26 72.39,16.26 72.9,15.75 77.98,15.75 79.5,14.22 92.71,14.22 98.55,20.07 QG1.8
OK1  (via drill 0.61)
  Top 0.254: v62.48,73.15 62.48,75.69 IC20.1
  Bottom 0.254: v62.48,73.15 60.2,73.15 59.69,72.64 27.94,72.64 26.67,71.37 IC15.19
OK2  (via drill 0.61)
  Top 0.254: v60.45,72.14 61.47,73.15 61.47,77.22 62.48,78.23 IC20.2
  Bottom 0.254: v60.45,72.14 42.67,72.14 41.91,71.37 IC16.19
OK3  (via drill 0.61)
  Top 0.254: v34.8,102.62 36.83,100.58 36.83,91.95 37.85,90.93 v37.85,81.79
  Bottom 0.254: v34.8,102.62 32.26,102.62 29.46,105.41 27.69,105.41 26.67,104.39 IC17.19 | v37.85,81.79 38.35,82.3 61.47,82.3 62.23,81.53 IC20.3
OK4  (via drill 0.61)
  Top 0.254: v52.58,84.33 52.58,92.71 41.66,103.63 IC18.19
  Bottom 0.254: v52.58,84.33 54.1,82.8 61.47,82.8 62.23,83.57 IC20.4
OK5
  Top 0.254: IC20.5 64.52,86.87 65.28,87.63 65.28,95.25 56.9,103.63 IC19.19
P1  (via drill 0.61)
  Top 0.254: v60.71,46.74 61.21,47.24 61.21,51.56 62.48,52.83 IC7.15 | v93.73,114.3 93.22,114.81 v93.22,116.33 | v76.45,115.57 76.45,57.66 73.91,55.12 v73.91,53.85
  Bottom 0.254: v60.71,46.74 35.05,46.74 34.29,45.97 IC13.1 | v93.73,114.3 95.25,114.3 IC25.1 | v93.22,116.33 92.71,115.82 82.04,115.82 81.79,115.57 v76.45,115.57 | v73.91,53.85 73.41,54.36 65.53,54.36 64.77,53.59 IC7.15
P2  (via drill 0.61)
  Top 0.254: 60.71,57.66 62.23,56.13 IC7.14 | v59.94,58.42 60.71,57.66 | v61.47,90.93 58.93,88.39 58.93,69.09 60.71,67.31 60.71,57.66
  Bottom 0.254: v59.94,58.42 58.93,59.44 27.43,59.44 26.67,58.67 IC13.9 | v61.47,90.93 61.98,90.42 64.77,90.42 65.28,90.93 66.55,90.93 67.31,90.17 75.44,90.17 75.44,120.4 81.53,126.49 87.38,126.49 87.63,126.75 IC25.9
PA1  (via drill 0.61)
  Top 0.254: v70.36,71.12 73.15,73.91 73.15,78.23 SV1.36
  Bottom 0.254: v70.36,71.12 69.34,70.1 35.05,70.1 34.29,70.87 IC15.2
PA2  (via drill 0.61)
  Top 0.254: v70.36,73.66 70.61,73.91 70.61,78.23 SV1.35
  Bottom 0.254: v70.36,73.66 69.34,73.66 68.83,74.17 50.55,74.17 50.04,74.68 39.88,74.68 39.12,75.44 34.8,75.44 34.29,75.95 IC15.4
PB1
  Bottom 0.254: IC15.6 34.29,81.03 35.05,80.26 70.36,80.26 70.61,80.01 72.39,80.01 73.15,80.77 SV1.34
PB2
  Bottom 0.254: IC15.8 34.29,86.61 35.05,87.38 50.8,87.38 53.34,84.84 67.56,84.84 70.61,81.79 SV1.33
PC1  (via drill 0.61)
  Top 0.254: v30.23,81.79 30.23,87.12 26.42,90.93 IC15.11
  Bottom 0.254: v30.23,81.79 32.26,79.76 68.33,79.76 70.61,77.47 74.17,77.47 74.93,78.23 74.93,83.31 74.17,83.31 SV1.32
PC2
  Bottom 0.254: IC15.13 26.67,86.61 27.94,87.88 70.36,87.88 70.61,87.63 71.63,87.63 72.39,86.87 72.39,84.33 71.63,84.33 SV1.31
PD1
  Bottom 0.254: IC15.15 26.67,81.03 29.97,77.72 45.47,77.72 45.97,78.23 46.48,78.23 47.24,77.47 69.85,77.47 70.36,76.96 74.42,76.96 75.44,77.98 75.44,85.85 74.17,85.85 SV1.30
PD2  (via drill 0.61)
  Top 0.254: v46.23,77.22 53.59,77.22 v53.59,85.85
  Bottom 0.254: v46.23,77.22 27.43,77.22 26.67,76.45 IC15.17 | v53.59,85.85 54.1,85.34 70.1,85.34 70.61,85.85 SV1.29
PE1  (via drill 0.61)
  Top 0.254: v69.09,71.12 72.39,74.42 72.39,87.63 73.15,88.39 SV1.28
  Bottom 0.254: v69.09,71.12 49.53,71.12 IC16.2
PE2  (via drill 0.61)
  Top 0.254: v69.6,74.68 69.85,74.93 69.85,87.63 70.61,88.39 SV1.27
  Bottom 0.254: v69.6,74.68 50.8,74.68 49.53,75.95 IC16.4
PF1  (via drill 0.61)
  Top 0.254: v50.04,93.98 50.04,82.55 49.28,81.79 IC16.6
  Bottom 0.254: v50.04,93.98 50.55,93.47 69.85,93.47 70.61,92.71 72.39,92.71 73.15,91.95 SV1.26
PF2  (via drill 0.61)
  Top 0.254: v46.23,91.69 46.23,87.88 47.24,86.87 IC16.8
  Bottom 0.254: v46.23,91.69 47.5,92.96 69.6,92.96 70.61,91.95 SV1.25
PH1
  Bottom 0.254: IC16.11 41.4,91.95 41.4,95.5 70.36,95.5 70.61,95.25 72.39,95.25 73.15,94.49 SV1.24
PH2  (via drill 0.61)
  Top 0.254: v42.42,92.46 42.42,87.63 41.66,86.87 IC16.13
  Bottom 0.254: v42.42,92.46 44.96,95 70.1,95 70.61,94.49 SV1.23
PJ1  (via drill 0.61)
  Top 0.254: v43.43,96.52 43.43,83.57 41.66,81.79 IC16.15
  Bottom 0.254: v43.43,96.52 44.7,97.79 72.39,97.79 73.15,97.03 SV1.22
PJ2  (via drill 0.61)
  Top 0.254: v47.5,96.52 43.94,92.96 43.94,78.99 41.66,76.71 IC16.17
  Bottom 0.254: v47.5,96.52 70.61,96.52 SV1.21
PK1
  Bottom 0.254: IC17.2 34.29,104.39 35.05,105.16 70.36,105.16 70.61,105.41 71.63,105.41 72.39,104.65 72.39,102.87 74.17,102.87 74.93,102.11 74.93,99.57 74.17,99.57 SV1.20
PK2  (via drill 0.61)
  Top 0.254: v35.81,104.14 35.81,106.93 34.04,108.71 IC17.4
  Bottom 0.254: v35.81,104.14 37.34,102.62 67.56,102.62 70.61,99.57 SV1.19
PL1  (via drill 0.61)
  Top 0.254: v37.08,104.14 37.08,109.98 34.54,112.52 34.54,113.28 34.04,113.79 IC17.6
  Bottom 0.254: v37.08,104.14 38.1,103.12 70.36,103.12 70.61,102.87 71.63,102.87 72.39,102.11 73.15,102.11 SV1.18
PL2
  Top 0.254: IC17.8 34.04,119.89 35.05,120.9 46.48,120.9 46.48,124.97 46.99,125.48 57.66,125.48 57.66,106.93 61.98,102.62 66.8,102.62 66.8,99.82 67.56,99.06 69.85,99.06 69.85,100.33 70.61,101.09 SV1.17
PM1
  Bottom 0.254: IC17.11 26.67,124.71 27.69,125.73 34.54,125.73 34.8,125.98 71.37,125.98 74.93,122.43 74.93,104.65 74.17,104.65 SV1.16
PM2
  Top 0.254: IC17.13 24.38,119.89 23.62,120.65 23.62,124.97 26.42,127.76 58.17,127.76 58.17,107.19 62.23,103.12 70.1,103.12 70.61,103.63 SV1.15
PN1  (via drill 0.61)
  Top 0.254: v27.69,126.75 27.69,116.08 26.42,114.81 IC17.15 | v68.07,127 68.58,126.49 68.58,109.98 70.61,107.95 73.15,107.95 73.15,107.19 SV1.14
  Bottom 0.254: v27.69,126.75 27.94,127 v68.07,127
PN2  (via drill 0.61)
  Top 0.254: v23.37,101.35 23.37,107.7 24.38,108.71 IC17.17 | v67.82,100.08 70.61,102.87 72.39,102.87 72.39,105.41 71.63,106.17 SV1.13
  Bottom 0.254: v23.37,101.35 24.64,100.08 v67.82,100.08
PP1  (via drill 0.61)
  Top 0.254: v53.09,107.95 49.53,104.39 IC18.2
  Bottom 0.254: v53.09,107.95 72.39,107.95 73.15,108.71 SV1.12
PP2
  Bottom 0.254: IC18.4 49.53,109.47 49.78,109.73 54.1,109.73 54.61,110.24 70.1,110.24 70.61,109.73 SV1.11
PR1
  Bottom 0.254: IC18.6 49.53,114.05 50.29,113.28 70.36,113.28 70.61,113.03 72.39,113.03 73.15,112.27 SV1.10
PR2  (via drill 0.61)
  Top 0.254: v51.05,111.76 51.05,117.09 49.28,118.87 IC18.8
  Bottom 0.254: v51.05,111.76 52.07,110.74 70.1,110.74 70.61,111.25 SV1.9
PS1  (via drill 0.61)
  Top 0.254: v71.37,123.44 72.39,122.43 72.39,115.57 73.15,114.81 SV1.8
  Bottom 0.254: v71.37,123.44 42.67,123.44 41.91,124.21 IC18.11
PS2
  Bottom 0.254: IC18.13 41.66,118.87 42.67,117.86 42.67,116.84 42.42,116.59 42.42,115.32 70.1,115.32 70.61,114.81 SV1.7
PT1  (via drill 0.61)
  Top 0.254: v69.6,112.27 70.36,113.03 74.93,113.03 74.93,115.57 74.17,116.33 SV1.6
  Bottom 0.254: v69.6,112.27 69.09,112.78 50.04,112.78 49.78,113.03 42.93,113.03 41.91,114.05 IC18.15
PT2  (via drill 0.61)
  Top 0.254: v43.43,116.33 43.43,111.51 41.66,109.73 IC18.17
  Bottom 0.254: v43.43,116.33 43.94,115.82 70.1,115.82 70.61,116.33 SV1.5
PU1
  Top 0.254: IC19.2 64.52,104.65 67.06,107.19 67.06,127.25 67.82,128.02 74.93,128.02 74.93,120.65 74.17,119.89 SV1.4
PU2  (via drill 0.61)
  Top 0.254: v66.04,116.84 66.04,111.25 64.52,109.73 IC19.4
  Bottom 0.254: v66.04,116.84 68.07,118.87 70.61,118.87 SV1.3
PV1  (via drill 0.61)
  Top 0.254: v61.47,117.09 61.47,115.82 62.48,114.81 IC19.6
  Bottom 0.254: v61.47,117.09 62.74,118.36 65.02,118.36 67.31,120.65 72.39,120.65 73.15,121.41 SV1.2
PV2
  Bottom 0.254: IC19.8 64.77,119.63 66.55,121.41 70.61,121.41 SV1.1
R1  (via drill 0.61)
  Top 0.254: v35.56,55.88 35.56,52.83 34.04,51.31 IC13.3 | v76.45,118.11 75.44,117.09 v75.44,58.93
  Bottom 0.254: v35.56,55.88 36.07,56.39 41.4,56.39 42.42,57.4 61.47,57.4 62.23,58.17 IC7.13 64.77,58.67 65.53,59.44 74.93,59.44 v75.44,58.93 | v76.45,118.11 81.79,118.11 82.04,118.36 94.49,118.36 95.25,119.13 IC25.3
R2  (via drill 0.61)
  Top 0.254: v27.43,60.96 27.43,54.86 26.42,53.85 IC13.11 | v53.59,63.75 55.37,61.98 v55.37,61.21 | v92.71,73.41 93.22,73.91 93.22,79.25 92.2,80.26 92.2,119.63 90.17,121.67 IC25.11 | v64.52,73.15 61.72,70.36 61.72,62.23 62.48,61.47 IC7.12
  Bottom 0.254: v27.43,60.96 30.23,63.75 v53.59,63.75 | v55.37,61.21 62.23,61.21 IC7.12 | v92.71,73.41 92.46,73.15 90.68,73.15 90.17,72.64 66.04,72.64 65.53,73.15 v64.52,73.15
S1  (via drill 0.61)
  Top 0.254: v40.89,62.74 34.29,56.13 IC13.5 | v107.44,125.48 108.46,124.46 108.46,70.61 v107.95,70.1
  Bottom 0.254: v40.89,62.74 61.72,62.74 62.23,63.25 IC7.11 64.77,63.75 65.53,64.52 108.46,64.52 108.46,69.09 107.95,69.6 v107.95,70.1 | v107.44,125.48 98.55,125.48 97.79,124.71 IC25.5
S2  (via drill 0.61)
  Top 0.254: v29.46,64.26 29.46,51.31 26.67,48.51 IC13.13 | v77.47,71.63 76.96,72.14 76.96,107.95 81.79,107.95 83.06,109.22 83.06,111.51 87.88,116.33 IC25.13 | v65.28,72.14 65.28,67.31 64.52,66.55 IC7.10
  Bottom 0.254: v29.46,64.26 30.99,65.79 62.23,65.79 IC7.10 | v77.47,71.63 76.96,72.14 v65.28,72.14
SEL0  (via drill 0.61)
  Top 0.254: v75.95,12.19 76.96,11.18 76.96,9.65 80.01,6.6 85.09,6.6 v85.09,35.56
  Bottom 0.254: v75.95,12.19 72.64,12.19 72.39,12.45 IC4.4 | v85.09,35.56 87.63,35.56 IC3.4
SEL1  (via drill 0.61)
  Top 0.254: v91.69,38.1 91.69,14.99 89.92,13.21 IC5.4
  Bottom 0.254: v91.69,38.1 90.17,38.1 IC3.5
SEL2  (via drill 0.61)
  Top 0.254: v85.85,36.58 86.11,36.83 v86.11,40.13
  Bottom 0.254: v85.85,36.58 73.15,36.58 72.39,35.81 IC6.4 | v86.11,40.13 86.36,40.39 87.63,40.39 IC3.6
SEL3  (via drill 0.61)
  Top 0.254: v85.34,55.88 85.6,55.63 v85.6,43.18
  Bottom 0.254: v85.34,55.88 83.82,57.4 73.15,57.4 72.39,58.17 IC7.4 | v85.6,43.18 87.63,43.18 IC3.7
SEL4  (via drill 0.61)
  Top 0.254: v84.07,38.1 85.09,39.12 85.09,41.4 86.61,42.93 86.61,56.39 v86.11,56.9
  Bottom 0.254: v84.07,38.1 82.55,38.1 IC3.12 | v86.11,56.9 87.38,58.17 87.63,58.17 IC8.4
T1  (via drill 0.61)
  Top 0.254: v52.58,66.8 52.58,46.99 51.82,46.23 IC14.1 | v100.33,111.25 100.33,82.3 98.81,80.77 98.81,71.88 99.31,71.37 v99.31,70.1
  Bottom 0.254: v52.58,66.8 54.1,68.33 62.23,68.33 IC7.9 64.77,68.83 65.53,69.6 98.81,69.6 v99.31,70.1 | v100.33,111.25 107.7,111.25 110.49,114.05 IC26.1
T2  (via drill 0.61)
  Top 0.254: v50.55,64.77 44.45,58.67 IC14.9 | v105.16,67.31 104.9,67.56 104.9,69.85 105.92,70.87 105.92,125.73 105.16,126.49 IC26.9
  Bottom 0.254: v50.55,64.77 50.8,65.02 69.09,65.02 | 69.09,65.02 69.85,65.79 IC7.7 | v105.16,67.31 104.9,67.06 92.2,67.06 90.17,65.02 69.09,65.02
TA1
  Bottom 0.254: IC21.2 95.25,76.45 93.98,77.72 82.3,77.72 81.79,78.23 SV2.36
TA2
  Top 0.254: IC21.8 88.14,89.41 88.14,92.2 87.38,92.96 82.55,92.96 82.55,88.39 81.79,87.63 80.01,87.63 80.01,80.01 79.25,79.25 SV2.35
TB1
  Bottom 0.254: IC21.4 95.25,81.53 94.49,82.3 87.12,82.3 86.61,81.79 81.79,81.79 SV2.34
TB2
  Bottom 0.254: IC21.10 87.63,83.57 86.61,82.55 80.01,82.55 79.25,81.79 SV2.33
TC1
  Bottom 0.254: IC21.6 95.25,86.11 93.98,84.84 87.12,84.84 86.36,84.07 81.79,84.07 SV2.32
TC2  (via drill 0.61)
  Top 0.254: v86.11,85.09 86.11,81.03 87.88,79.25 IC21.12
  Bottom 0.254: v86.11,85.09 80.01,85.09 79.25,84.33 SV2.31
TD1  (via drill 0.61)
  Top 0.254: v83.57,75.18 83.82,75.44 83.82,83.82 81.79,85.85 SV2.30
  Bottom 0.254: v83.57,75.18 109.73,75.18 110.49,75.95 IC22.2
TD2
  Bottom 0.254: IC22.8 102.87,88.65 102.11,87.88 82.04,87.88 81.79,87.63 80.77,87.63 80.01,86.87 79.25,86.87 SV2.29
TE1
  Bottom 0.254: IC22.4 110.49,81.03 109.73,80.26 83.57,80.26 83.06,79.76 82.04,79.76 81.79,80.01 78.23,80.01 77.47,80.77 77.47,87.63 80.01,87.63 80.77,88.39 SV2.28
TE2
  Bottom 0.254: IC22.10 103.12,84.33 102.11,85.34 102.11,87.38 104.9,87.38 105.92,88.39 105.92,90.17 80.01,90.17 79.25,89.41 SV2.27
TF1
  Bottom 0.254: IC22.6 110.49,86.61 106.17,90.93 81.79,90.93 SV2.26
TF2  (via drill 0.61)
  Top 0.254: v91.69,76.71 v91.69,78.74
  Bottom 0.254: v91.69,78.74 92.71,79.76 102.11,79.76 102.87,78.99 IC22.12 | v91.69,76.71 91.19,77.22 78.49,77.22 76.96,78.74 76.96,90.93 78.23,90.93 SV2.25
TH1
  Bottom 0.254: IC23.2 95.25,96.27 94.49,95.5 82.8,95.5 81.79,94.49 SV2.24
TH2  (via drill 0.61)
  Top 0.254: v85.09,108.71 81.79,105.41 77.47,105.41 77.47,95.25 78.23,94.49 SV2.23
  Bottom 0.254: v85.09,108.71 87.38,108.71 87.63,108.97 IC23.8
TJ1  (via drill 0.61)
  Top 0.254: v84.33,100.58 82.55,98.81 82.55,97.79 81.79,97.03 SV2.22
  Bottom 0.254: v84.33,100.58 94.49,100.58 95.25,101.35 IC23.4
TJ2  (via drill 0.61)
  Top 0.254: v86.11,104.14 85.34,103.38 85.34,98.81 81.79,95.25 79.25,95.25 79.25,96.01 SV2.21
  Bottom 0.254: v86.11,104.14 87.63,104.14 IC23.10
TK1  (via drill 0.61)
  Top 0.254: v96.77,111.25 98.3,109.73 98.3,107.95 97.54,107.19 IC23.6 | v86.11,111.25 86.11,105.41 82.55,101.85 82.55,100.33 81.79,99.57 SV2.20
  Bottom 0.254: v86.11,111.25 v96.77,111.25
TK2
  Bottom 0.254: IC23.12 87.63,99.31 87.38,99.57 82.55,99.57 81.79,100.33 80.77,100.33 80.01,99.57 79.25,99.57 SV2.19
TL1
  Bottom 0.254: IC24.2 110.49,96.77 109.73,97.54 99.82,97.54 97.28,95 84.07,95 81.79,92.71 78.23,92.71 77.47,93.47 77.47,100.33 80.01,100.33 80.77,101.09 SV2.18
TL2
  Bottom 0.254: IC24.8 105.41,109.47 106.17,110.24 115.06,110.24 119.38,105.92 119.38,102.62 93.47,102.62 92.46,103.63 90.68,103.63 90.17,103.12 83.57,103.12 83.06,103.63 82.55,103.63 81.79,102.87 80.01,102.87 79.25,102.11 SV2.17
TM1  (via drill 0.61)
  Top 0.254: v80.26,97.79 80.01,98.04 80.01,102.87 80.77,103.63 SV2.16
  Bottom 0.254: v80.26,97.79 89.92,97.79 92.2,100.08 109.22,100.08 110.49,101.35 IC24.4
TM2
  Bottom 0.254: IC24.10 102.87,104.39 102.11,105.16 82.04,105.16 81.79,105.41 80.01,105.41 79.25,104.65 SV2.15
TN1
  Bottom 0.254: IC24.6 110.49,106.93 109.73,107.7 82.3,107.7 81.79,107.19 SV2.14
TN2  (via drill 0.61)
  Top 0.254: v102.36,110.24 102.36,100.33 103.12,99.57 IC24.12
  Bottom 0.254: v102.36,110.24 84.07,110.24 81.79,107.95 80.01,107.95 79.25,107.19 SV2.13
TP1
  Bottom 0.254: IC25.2 95.25,116.59 93.98,115.32 84.07,115.32 81.79,113.03 80.77,113.03 80.01,112.27 80.01,109.73 80.77,109.73 SV2.12
TP2
  Top 0.254: IC25.8 87.63,129.29 80.01,129.29 80.01,116.33 79.25,115.57 77.47,115.57 77.47,110.49 78.23,109.73 SV2.11
TR1  (via drill 0.61)
  Top 0.254: v98.3,112.27 98.3,120.65 97.54,121.41 IC25.4
  Bottom 0.254: v98.3,112.27 81.79,112.27 SV2.10
TR2
  Top 0.254: IC25.10 87.88,123.95 87.12,123.19 87.12,121.41 88.14,120.4 90.68,120.4 90.68,118.87 89.66,117.86 87.63,117.86 82.55,112.78 82.55,111.25 81.79,110.49 79.25,110.49 79.25,111.25 SV2.9
TS1  (via drill 0.61)
  Top 0.254: v87.12,125.48 82.55,120.9 82.55,115.57 81.79,114.81 SV2.8
  Bottom 0.254: v87.12,125.48 93.98,125.48 95.25,126.75 IC25.6
TS2
  Top 0.254: IC25.12 87.88,118.87 82.04,113.03 79.25,113.03 79.25,113.79 SV2.7
TT1
  Bottom 0.254: IC26.2 110.49,117.09 109.73,117.86 82.3,117.86 81.79,117.35 SV2.6
TT2
  Top 0.254: IC26.8 102.87,129.79 98.81,129.79 98.81,130.3 98.04,131.06 77.47,131.06 77.47,118.11 78.23,117.35 SV2.5
TU1
  Bottom 0.254: IC26.4 110.49,121.67 109.22,120.4 82.3,120.4 81.79,119.89 SV2.4
TU2
  Bottom 0.254: IC26.10 102.87,124.21 102.11,123.44 81.03,123.44 80.01,122.43 80.01,119.89 79.25,119.89 SV2.3
TV1
  Bottom 0.254: IC26.6 110.49,126.75 106.68,122.94 82.3,122.94 81.79,122.43 SV2.2
TV2
  Top 0.254: IC26.12 103.12,119.89 98.3,124.71 98.3,130.05 97.79,130.56 79.25,130.56 79.25,122.43 SV2.1
U1  (via drill 0.61)
  Top 0.254: v78.99,48.77 79.5,49.28 79.5,52.07 80.26,52.83 IC8.15 | v114.55,57.66 114.3,57.91 114.3,117.35 112.78,118.87 IC26.3
  Bottom 0.254: IC14.3 52.07,50.55 53.85,48.77 v78.99,48.77 79.25,48.51 80.26,47.5 104.39,47.5 v114.55,57.66
U2  (via drill 0.61)
  Top 0.254: v74.93,47.75 75.95,48.77 v75.95,55.88 | v106.43,70.1 106.43,128.02 102.87,128.02 102.36,127.51 102.36,123.19 103.12,122.43 IC26.11 | v85.6,66.04 83.57,64.01 83.57,57.66 82.3,56.39 IC8.14
  Bottom 0.254: v74.93,47.75 74.42,48.26 53.59,48.26 52.58,49.28 48.26,49.28 44.45,53.09 IC14.11 | v75.95,55.88 76.45,55.37 80.26,55.37 IC8.14 | v106.43,70.1 105.92,69.6 104.65,69.6 102.62,67.56 87.12,67.56 v85.6,66.04
V1  (via drill 0.61)
  Top 0.254: v78.74,56.39 80.26,57.91 IC8.13 | v115.32,66.04 115.32,121.41 112.78,123.95 IC26.5
  Bottom 0.254: v78.74,56.39 78.23,56.9 52.83,56.9 52.07,56.13 IC14.5 | v115.32,66.04 108.71,59.44 83.31,59.44 82.55,58.67 IC8.13
V2  (via drill 0.61)
  Top 0.254: v77.47,46.74 77.72,46.99 77.72,57.91 80.26,60.45 IC8.12 82.3,61.47 83.06,62.23 83.06,64.77 85.09,66.8 85.09,89.92 v87.12,91.95 | v99.31,92.71 99.31,116.59 102.87,116.59 IC26.13
  Bottom 0.254: v77.47,46.74 74.68,46.74 73.66,47.75 60.45,47.75 59.94,47.24 45.21,47.24 44.45,48.01 IC14.13 | v99.31,92.71 98.55,91.95 v87.12,91.95
VCC
  Top 0.254: IC6.16 62.48,28.45 61.72,29.21 61.72,49.53 62.48,50.29 IC7.16 | IC3.16 82.3,28.45 83.06,29.21 83.06,49.53 82.3,50.29 IC8.16 82.3,51.31 84.33,53.34 84.33,63.5 86.61,65.79 86.61,71.88 87.88,73.15 IC21.14 | IC23.14 87.88,94.49 87.12,95.25 87.12,113.03 87.88,113.79 IC25.14 | IC1.5 107.7,41.15 108.46,41.91 108.46,62.23 107.7,62.99 IC2.5 105.66,64.01 104.14,65.53 104.14,73.15 IC22.14 103.12,74.17 102.36,74.93 102.36,92.71 103.12,93.47 IC24.14 | IC19.20 56.9,101.09 57.66,100.33 57.66,85.09 56.9,84.33 IC20.11 54.86,83.31 54.86,81.79 IC20.12 54.86,80.77 54.1,80.01 54.1,77.47 54.86,76.71 IC20.14 54.61,75.95 54.61,75.18 47.5,75.18 46.48,74.17 46.48,73.91 41.66,69.09 IC16.20 | 23.62,24.13 24.38,24.89 IC11.14 | 23.62,24.13 23.62,6.35 24.38,5.59 IC9.14 | 23.62,24.13 23.62,41.15 24.38,41.91 24.38,45.21 IC13.14 24.38,46.23 23.62,46.99 23.62,67.31 24.38,68.07 IC15.20
  Bottom 0.254: IC7.16 64.77,50.55 66.04,49.28 78.23,49.28 79.5,50.55 80.01,50.55 IC8.16 | IC23.14 90.17,93.73 90.93,92.96 98.3,92.96 99.06,93.73 102.87,93.73 IC24.14 | IC25.14 90.17,114.05 90.93,113.28 102.11,113.28 102.87,114.05 IC26.14 | IC21.14 90.17,73.91 90.93,74.68 102.11,74.68 102.87,73.91 IC22.14 | IC15.20 26.67,68.33 27.43,67.56 38.61,67.56 39.37,68.33 IC16.20 | 38.61,100.58 27.43,100.58 26.67,101.35 IC17.20 | 38.61,100.58 39.37,101.35 IC18.20 | 38.61,100.58 53.85,100.58 54.61,101.35 IC19.20 | IC13.14 26.67,45.47 27.43,44.7 41.15,44.7 41.91,45.47 IC14.14 | 36.83,26.42 31.75,26.42 31.24,25.91 26.92,25.91 26.67,25.65 IC11.14 | 36.83,26.42 37.85,25.4 41.91,25.4 IC12.14 | IC9.14 26.67,4.83 27.43,4.06 41.15,4.06 41.91,4.83 IC10.14 44.45,4.83 45.21,4.06 61.47,4.06 62.23,4.83 IC4.16 64.77,5.33 65.53,6.1 79.25,6.1 | 79.25,6.1 80.01,5.33 IC5.16 | 79.25,6.1 97.79,6.1 98.55,5.33 QG1.14 | 36.83,26.42 37.85,27.43 38.35,27.43 38.86,26.92 61.47,26.92 62.23,27.69 IC6.16
XMIT  (via drill 0.61)
  Top 0.254: IC4.6 72.14,18.29 72.9,19.05 72.9,39.37 72.14,40.13 IC6.6 72.14,41.15 72.9,41.91 72.9,64.77 | v92.71,20.57 92.71,24.64 98.04,29.97 IC1.14 | v66.29,89.92 68.07,88.14 68.07,70.87 69.34,69.6 72.9,69.6 72.9,64.77 | 72.9,64.77 72.14,64.01 IC7.6
  Bottom 0.254: IC4.6 72.39,17.53 72.64,17.27 79.5,17.27 80.01,16.76 86.87,16.76 87.63,17.53 IC5.6 90.17,18.03 v92.71,20.57 | IC7.6 72.39,63.25 73.15,62.48 86.87,62.48 87.63,63.25 IC8.6 | v66.29,89.92 58.42,89.92 57.15,91.19 IC20.8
